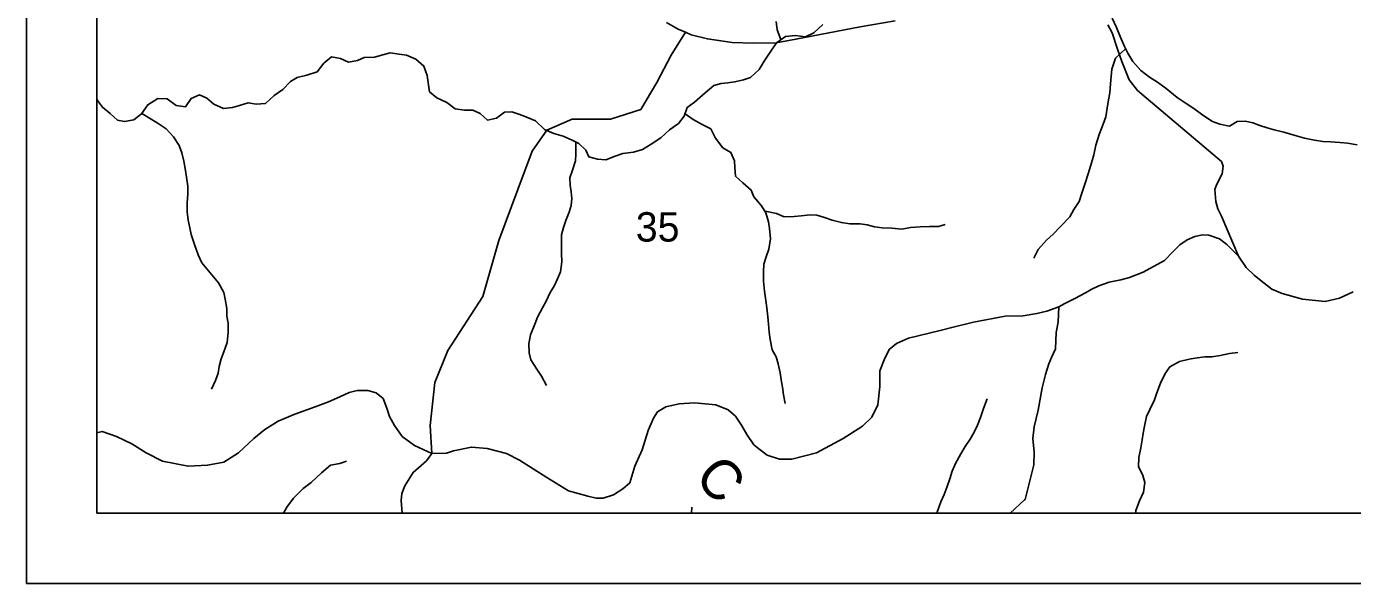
# Model space of a CAD drawing. Extents: x 0 to 34, y 0 to 22.
# Drawn here: x 2 to 3.888, y 14 to 14.793 of the extents above; entities that cross this region are included whole.
import ezdxf

# ---------------------------------------------------------------- set-up
doc = ezdxf.new("R2010")
doc.units = 0
for name, color, linetype in [('GM_X_County_Road', 7, 'Continuous'), ('GM_X_County_Road_Text', 7, 'Continuous'), ('GM_X_Minor_River', 7, 'Continuous'), ('GM_X_Section_Text', 7, 'Continuous'), ('GM_X_Township_Road', 7, 'Continuous'), ('SH_Data', 7, 'Continuous')]:
    doc.layers.add(name, color=color, linetype=linetype)

msp = doc.modelspace()

# ---------------------------------------------------------------- linework, layer by layer
at = {"layer": 'GM_X_County_Road'}
for points in [[(2.911, 14.7991), (2.9279, 14.7897), (2.9381, 14.7852), (2.9461, 14.7817), (2.9695, 14.7756), (3.0046, 14.7705), (3.0355, 14.7696), (3.0673, 14.77), (3.0954, 14.7752), (3.1871, 14.7929), (3.2367, 14.8014)], [(3.5393, 14.7958), (3.5457, 14.7845), (3.5528, 14.7625), (3.5592, 14.7436), (3.57, 14.7176), (3.5817, 14.7022), (3.6891, 14.6114), (3.7011, 14.6009), (3.7039, 14.5942), (3.7023, 14.5837), (3.694, 14.568), (3.6919, 14.5612), (3.6933, 14.5443), (3.6961, 14.5338), (3.7015, 14.523), (3.7255, 14.4664)], [(2.1, 14.2146), (2.1075, 14.2165), (2.1279, 14.2092), (2.1498, 14.199), (2.1703, 14.1859), (2.1936, 14.1742), (2.2301, 14.1669), (2.2578, 14.1684), (2.2811, 14.1728), (2.3016, 14.1859), (2.3235, 14.2063), (2.3395, 14.2194), (2.3585, 14.2311), (2.3818, 14.2413), (2.411, 14.2515), (2.43, 14.2588), (2.446, 14.2661), (2.4592, 14.272), (2.4708, 14.2749), (2.4859, 14.275), (2.4976, 14.2715), (2.5079, 14.2633), (2.5129, 14.2497), (2.5166, 14.2379), (2.5237, 14.2249), (2.5349, 14.2094), (2.5526, 14.1964), (2.5772, 14.185), (2.5978, 14.1857), (2.608, 14.1888), (2.6335, 14.1943), (2.6556, 14.1925), (2.6832, 14.1852), (2.7018, 14.1757), (2.741, 14.1511), (2.7714, 14.1319), (2.7992, 14.1246), (2.8108, 14.1217), (2.821, 14.1217), (2.8356, 14.1261), (2.8488, 14.1348), (2.859, 14.1436), (2.8663, 14.1669), (2.8765, 14.1903), (2.8852, 14.218), (2.8925, 14.2355), (2.8984, 14.2443), (2.91, 14.2516), (2.929, 14.2559), (2.9509, 14.2574), (2.9815, 14.2545), (2.9991, 14.2472), (3.0093, 14.2384), (3.018, 14.2253), (3.0253, 14.2122), (3.0355, 14.1976), (3.0428, 14.1918), (3.0545, 14.183), (3.072, 14.1772), (3.0895, 14.1772), (3.1245, 14.1859), (3.1625, 14.2064), (3.1902, 14.2239), (3.2033, 14.237), (3.2121, 14.2545), (3.215, 14.2808), (3.215, 14.3027), (3.2209, 14.3187), (3.2281, 14.3333), (3.2384, 14.342), (3.2559, 14.3493), (3.301, 14.3604), (3.3173, 14.3647), (3.3482, 14.3721), (3.3932, 14.3807), (3.419, 14.3813), (3.4385, 14.3845), (3.4527, 14.388), (3.4698, 14.3942), (3.4784, 14.3986), (3.4923, 14.4059), (3.5076, 14.4139), (3.5156, 14.4189), (3.5269, 14.4239), (3.5414, 14.4293), (3.5581, 14.4325), (3.5703, 14.4357), (3.5898, 14.4434), (3.6201, 14.4601), (3.6318, 14.4723), (3.6418, 14.4823), (3.6522, 14.4895), (3.6635, 14.494), (3.6743, 14.4967), (3.6834, 14.4963), (3.6983, 14.4909), (3.7087, 14.4827), (3.7255, 14.4664)], [(3.7255, 14.4664), (3.7363, 14.4501), (3.7476, 14.4393), (3.7553, 14.433), (3.7731, 14.4191), (3.7877, 14.4132), (3.8168, 14.4049), (3.8489, 14.4017), (3.8693, 14.4063), (3.8887, 14.4153)], [(2.5346, 14.1), (2.5332, 14.1181), (2.5343, 14.1284), (2.5386, 14.139), (2.5507, 14.1581), (2.5694, 14.1746), (2.5772, 14.185)]]:
    msp.add_lwpolyline(points, dxfattribs=at)
at = {"layer": 'GM_X_Minor_River'}
msp.add_line((2.9468, 14.1), (2.9472, 14.1086), dxfattribs=at)
for points in [[(3.0739, 14.7746), (3.0689, 14.7884), (3.0674, 14.8006)], [(3.5456, 14.8052), (3.552, 14.792), (3.5572, 14.779), (3.5632, 14.765), (3.5678, 14.7555), (3.5753, 14.7437), (3.5866, 14.7308), (3.5986, 14.7213), (3.6103, 14.714), (3.6224, 14.7049), (3.6383, 14.6923), (3.6511, 14.6839), (3.662, 14.6767), (3.6749, 14.6672), (3.6884, 14.658), (3.699, 14.6542), (3.7126, 14.6515), (3.7236, 14.6579), (3.7354, 14.6586), (3.7459, 14.6559), (3.7558, 14.6521), (3.7663, 14.649), (3.7762, 14.6463), (3.7902, 14.6429), (3.806, 14.6383), (3.8196, 14.6344), (3.8336, 14.6313), (3.8457, 14.6294), (3.8567, 14.629), (3.8699, 14.6282), (3.8809, 14.627), (3.8945, 14.6247)], [(2.6104, 14.6761), (2.6236, 14.6741), (2.6353, 14.6741), (2.6459, 14.6695), (2.6565, 14.66), (2.6693, 14.663), (2.6807, 14.6713), (2.6909, 14.672), (2.7011, 14.6685), (2.711, 14.6647), (2.7245, 14.659), (2.7374, 14.6464), (2.7506, 14.6411), (2.7638, 14.6372), (2.7767, 14.6315), (2.7865, 14.6269), (2.7963, 14.6174), (2.8004, 14.6075), (2.8129, 14.6044), (2.825, 14.6033), (2.8379, 14.6085), (2.8492, 14.6123), (2.864, 14.6145), (2.8769, 14.6182), (2.8894, 14.6258), (2.903, 14.6348), (2.9155, 14.6461), (2.9281, 14.6552), (2.9364, 14.6658), (2.9406, 14.6779), (2.9512, 14.6854), (2.9661, 14.699), (2.9786, 14.7092), (2.9888, 14.7122), (2.9986, 14.7133), (3.0085, 14.7144), (3.021, 14.7174), (3.0308, 14.7207), (3.043, 14.7321), (3.0502, 14.7438), (3.0589, 14.7566), (3.0677, 14.7703), (3.0806, 14.7793), (3.0946, 14.7804), (3.109, 14.7788), (3.1207, 14.7841), (3.1336, 14.7962)], [(2.1, 14.6901), (2.1012, 14.6879), (2.108, 14.6784), (2.1189, 14.6692), (2.1295, 14.6601), (2.1397, 14.6578), (2.1529, 14.6604), (2.1639, 14.669), (2.1727, 14.6819), (2.1871, 14.6906), (2.2003, 14.6901), (2.2132, 14.681), (2.2264, 14.6787), (2.2344, 14.6908), (2.2461, 14.696), (2.2567, 14.6914), (2.2669, 14.6827), (2.2805, 14.6766), (2.2934, 14.678), (2.3032, 14.681), (2.3157, 14.6848), (2.327, 14.6825), (2.3403, 14.6839), (2.3528, 14.6949), (2.365, 14.7035), (2.3756, 14.7149), (2.3851, 14.7205), (2.3991, 14.7239), (2.4138, 14.7287), (2.4234, 14.7412), (2.434, 14.7499), (2.4472, 14.7476), (2.4585, 14.7426), (2.471, 14.7448), (2.4809, 14.749), (2.4953, 14.7497), (2.5074, 14.753), (2.5176, 14.7556), (2.5305, 14.7537), (2.541, 14.7525), (2.5543, 14.7468), (2.5656, 14.7369), (2.5704, 14.7236), (2.5723, 14.7103), (2.5738, 14.7005), (2.5843, 14.6917), (2.5983, 14.6852), (2.6104, 14.6761)], [(3.5648, 14.7617), (3.5503, 14.7484), (3.545, 14.7325), (3.5442, 14.7222), (3.5434, 14.7116), (3.5422, 14.6988), (3.5406, 14.6889), (3.5383, 14.6768), (3.5364, 14.6647), (3.533, 14.6541), (3.5272, 14.6397), (3.5226, 14.6242), (3.5195, 14.6105), (3.5153, 14.5958), (3.5115, 14.5837), (3.5073, 14.57), (3.5027, 14.556), (3.4985, 14.5439), (3.4909, 14.5329), (3.4852, 14.5224), (3.4723, 14.5084), (3.4616, 14.4974), (3.4521, 14.4891), (3.4404, 14.4755), (3.4343, 14.4634)], [(2.1641, 14.6692), (2.1753, 14.6626), (2.1862, 14.6561), (2.199, 14.6477), (2.2092, 14.6363), (2.2171, 14.6237), (2.2209, 14.6135), (2.2238, 14.6014), (2.2264, 14.5881), (2.2283, 14.5752), (2.2298, 14.5657), (2.2297, 14.5547), (2.2285, 14.5422), (2.2285, 14.5293), (2.2303, 14.5176), (2.2326, 14.5066), (2.2344, 14.4971), (2.2393, 14.4827), (2.2445, 14.4679), (2.2494, 14.4569), (2.2731, 14.4284), (2.2807, 14.4143), (2.2829, 14.4048), (2.2851, 14.3915), (2.2854, 14.3806), (2.2869, 14.3707), (2.2873, 14.3578), (2.2857, 14.3434), (2.2807, 14.3298), (2.2769, 14.32), (2.2742, 14.309), (2.2727, 14.2995), (2.2692, 14.2893), (2.2635, 14.2768)], [(2.9375, 14.6688), (2.9489, 14.6608), (2.9621, 14.6539), (2.9742, 14.6474), (2.9809, 14.6341), (2.9915, 14.6205), (3.0028, 14.614), (3.0081, 14.6022), (3.0084, 14.5927), (3.0095, 14.5802), (3.0197, 14.5707), (3.0317, 14.5604), (3.0355, 14.5509), (3.0464, 14.538), (3.0528, 14.5281), (3.0565, 14.5149), (3.058, 14.5054), (3.0591, 14.491), (3.0568, 14.4762), (3.0529, 14.4652), (3.0499, 14.455), (3.0491, 14.444), (3.0494, 14.4307), (3.0509, 14.4163), (3.0527, 14.4031), (3.0542, 14.3928), (3.0553, 14.3799), (3.0564, 14.3693), (3.0575, 14.358), (3.0586, 14.3473), (3.0615, 14.3329), (3.0672, 14.323), (3.0702, 14.3128), (3.0728, 14.2999), (3.0742, 14.2901), (3.0761, 14.2798), (3.0779, 14.2688), (3.0802, 14.2563)], [(2.782, 14.629), (2.7819, 14.6114), (2.7815, 14.6019), (2.7772, 14.5887), (2.7734, 14.5777), (2.7738, 14.5675), (2.7752, 14.558), (2.7763, 14.5485), (2.7752, 14.5386), (2.7725, 14.5288), (2.7679, 14.5171), (2.7645, 14.5069), (2.7618, 14.4966), (2.7617, 14.4701), (2.762, 14.4583), (2.7601, 14.444), (2.7562, 14.4341), (2.7517, 14.4243), (2.7456, 14.4144), (2.7399, 14.4023), (2.7345, 14.3925), (2.7273, 14.3793), (2.7239, 14.3694), (2.7174, 14.3543), (2.715, 14.3414), (2.7158, 14.3285), (2.718, 14.3187), (2.7266, 14.3054), (2.733, 14.2951), (2.7402, 14.2818)], [(3.0514, 14.5303), (3.0676, 14.5269), (3.0785, 14.5224), (3.0929, 14.5227), (3.1031, 14.5238), (3.1156, 14.5252), (3.1254, 14.5244), (3.136, 14.5214), (3.147, 14.5175), (3.1602, 14.5141), (3.1723, 14.5121), (3.1867, 14.5125), (3.1969, 14.5109), (3.2071, 14.5078), (3.218, 14.5067), (3.232, 14.5059), (3.246, 14.5047), (3.2585, 14.5069), (3.2725, 14.508), (3.2858, 14.5083), (3.2982, 14.5083), (3.3081, 14.5113)], [(3.5794, 14.1), (3.5793, 14.104), (3.5847, 14.1176), (3.5904, 14.1301), (3.5923, 14.1437), (3.5894, 14.154), (3.5833, 14.1665), (3.5834, 14.1794), (3.5865, 14.193), (3.5884, 14.2048), (3.59, 14.2142), (3.5915, 14.2241), (3.5946, 14.2377), (3.5995, 14.2479), (3.606, 14.2615), (3.6091, 14.2714), (3.6144, 14.2854), (3.6209, 14.299), (3.6278, 14.3088), (3.6414, 14.3164), (3.6554, 14.3193), (3.6668, 14.3216), (3.6774, 14.3227), (3.6876, 14.323), (3.6993, 14.3249), (3.7129, 14.3278), (3.7247, 14.3289)], [(3.296, 14.1), (3.2971, 14.1028), (3.3017, 14.1164), (3.3063, 14.1266), (3.3105, 14.138), (3.3143, 14.1493), (3.3178, 14.1599), (3.3227, 14.1709), (3.33, 14.1845), (3.3364, 14.1951), (3.3433, 14.2057), (3.349, 14.2155), (3.3539, 14.2257), (3.3581, 14.2363), (3.3627, 14.2492), (3.3677, 14.2632)], [(2.3659, 14.1), (2.3707, 14.1085), (2.3802, 14.1214), (2.3939, 14.1353), (2.4052, 14.144), (2.42, 14.1576), (2.433, 14.1685), (2.4462, 14.1708), (2.4557, 14.1741)]]:
    msp.add_lwpolyline(points, dxfattribs=at)
at = {"layer": 'GM_X_Township_Road'}
for points in [[(2.5772, 14.185), (2.5746, 14.2248), (2.5814, 14.2862), (2.5996, 14.3317), (2.6496, 14.409), (2.6723, 14.4886), (2.6996, 14.5613), (2.7201, 14.6159), (2.7406, 14.6455), (2.777, 14.6614), (2.8315, 14.6614), (2.8747, 14.675), (2.8975, 14.7137), (2.9179, 14.7523), (2.9381, 14.7852)], [(3.4005, 14.1), (3.4209, 14.119), (3.4217, 14.1198), (3.434, 14.1688), (3.4344, 14.1871), (3.4328, 14.2066), (3.4344, 14.2231), (3.4401, 14.2471), (3.446, 14.2787), (3.4505, 14.2979), (3.4553, 14.3127), (3.4595, 14.3221), (3.465, 14.3341), (3.4661, 14.3575), (3.4686, 14.3723), (3.4698, 14.3942)]]:
    msp.add_lwpolyline(points, dxfattribs=at)
at = {"layer": 'SH_Data'}
for p, q in [((2, 21), (2, 14)), ((2.1, 20.9), (2.1, 14.1)), ((2.1, 14.1), (8.9, 14.1)), ((2, 14), (9, 14))]:
    msp.add_line(p, q, dxfattribs=at)

# ---------------------------------------------------------------- texts
at = {"layer": 'GM_X_County_Road_Text'}
msp.add_text('C', height=0.0568, rotation=312.4491, dxfattribs=at).set_placement((2.9491, 14.15))
at = {"layer": 'GM_X_Section_Text'}
msp.add_text('35', height=0.04186, rotation=0, dxfattribs=at).set_placement((2.8674, 14.487))

doc.saveas('drawing.dxf')
